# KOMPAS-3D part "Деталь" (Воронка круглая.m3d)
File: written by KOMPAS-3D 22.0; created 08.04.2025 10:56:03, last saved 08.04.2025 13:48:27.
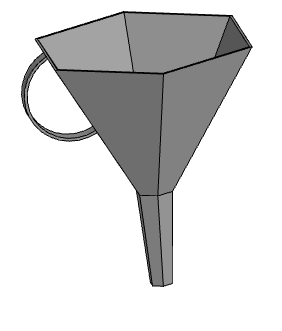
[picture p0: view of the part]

Document properties: Автор: Admin; Полное имя файла: D:\28.11.2016\Абилимпикс\2025\Воронка круглая.m3d

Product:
- Body: Тело 8
    Масса: 0.195689
- Body: Тело 10
    Масса: 0.007182
- Part/product: Деталь
    Масса: 0.197153

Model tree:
1. Эскиз:5
2. Смещенная плоскость:2
     Расстояние = 80
3. Эскиз:6
4. Элемент по сечениям:5
5. Эскиз:7  (with: Элемент по сечениям:5)
6. Эскиз:8  (with: Элемент по сечениям:5)
7. Элемент по сечениям:6
8. Смещенная плоскость:3  (with: Элемент по сечениям:5)
     Расстояние = 50
9. Эскиз:9
10. Элемент по сечениям:7
11. Эскиз:10  (with: Элемент по сечениям:7)
12. Элемент по сечениям:8
13. Эскиз:12
14. Элемент выдавливания:8
     Расстояние 1 = 8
